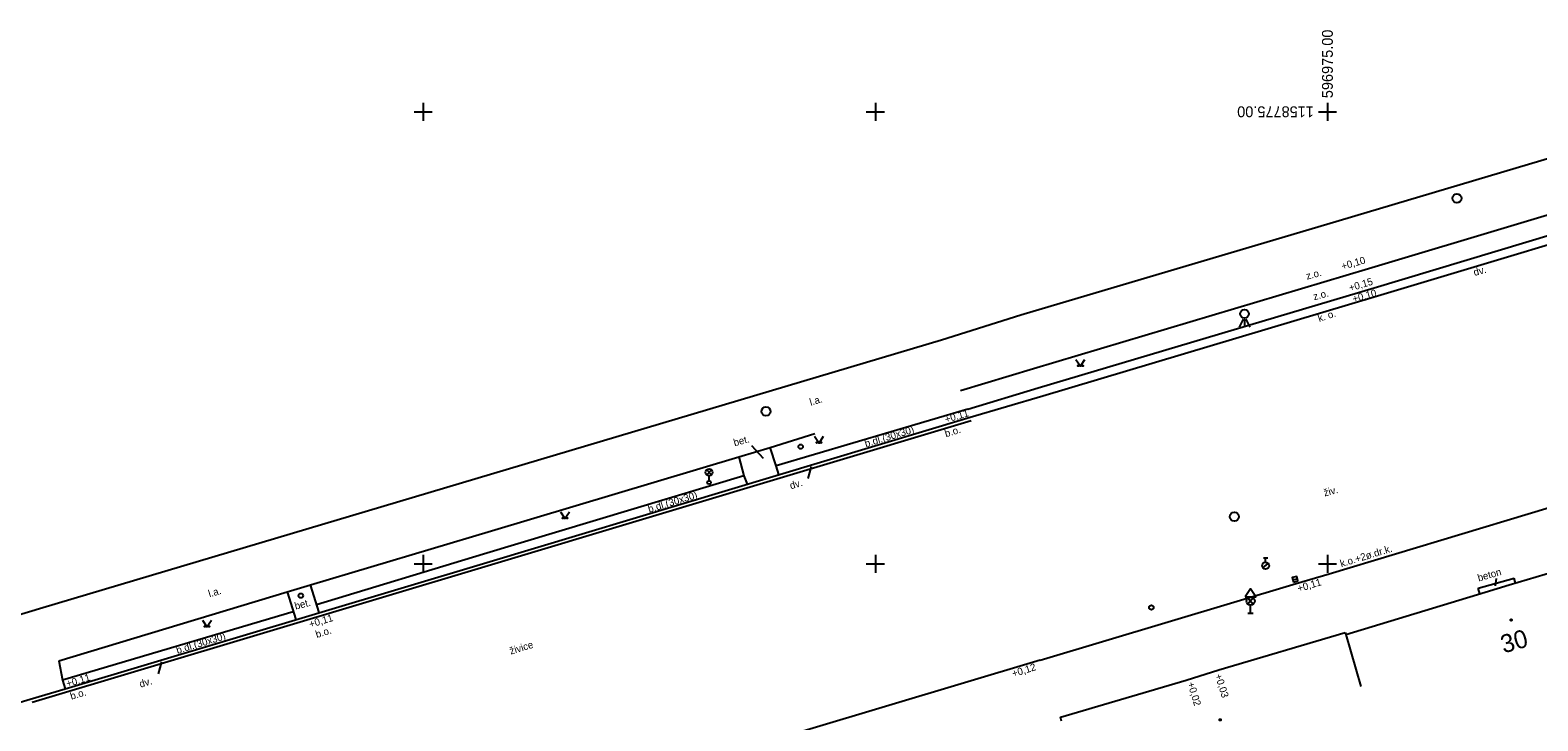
# Model space of a CAD drawing. Extents: x -597333 to -596488, y -1158921 to -1158644.
# Drawn here: x -597046.7 to -596963.4, y -1158808.7 to -1158770.5 of the extents above; entities that cross this region are included whole.
import ezdxf

# ---------------------------------------------------------------- set-up
doc = ezdxf.new("R2010")
doc.units = 0
for name, color, linetype in [('Vrstva 10', 7, 'Continuous'), ('Vrstva 14', 7, 'Continuous'), ('Vrstva 15', 7, 'Continuous'), ('Vrstva 23', 7, 'Continuous'), ('Vrstva 24', 7, 'Continuous'), ('Vrstva 25', 7, 'Continuous'), ('Vrstva 29', 7, 'Continuous'), ('Vrstva 4', 7, 'Continuous'), ('Vrstva 43', 7, 'Continuous'), ('Vrstva 44', 7, 'Continuous'), ('Vrstva 49', 7, 'Continuous'), ('Vrstva 5', 7, 'Continuous'), ('Vrstva 50', 7, 'Continuous'), ('Vrstva 52', 7, 'Continuous'), ('Vrstva 62', 7, 'Continuous'), ('Vrstva 7', 7, 'Continuous')]:
    doc.layers.add(name, color=color, linetype=linetype)

msp = doc.modelspace()

# ---------------------------------------------------------------- linework, layer by layer
at = {"layer": 'Vrstva 10'}
msp.add_line((-597046.039, -1158802.404), (-596996.341, -1158787.614), dxfattribs=at)
for points in [[(-596974.355, -1158781.01), (-596957.875, -1158776.104), (-596940.288, -1158770.868)], [(-596996.341, -1158787.614), (-596991.949, -1158786.233), (-596974.355, -1158781.01)], [(-597053.2, -1158804.562), (-597046.039, -1158802.404)]]:
    msp.add_lwpolyline(points, dxfattribs=at)
at = {"layer": 'Vrstva 14'}
for points in [[(-596988.908, -1158788.694), (-596988.658, -1158789.069), (-596988.408, -1158788.694)], [(-597003.365, -1158792.945), (-597003.115, -1158793.32), (-597002.865, -1158792.945)], [(-597017.415, -1158797.12), (-597017.165, -1158797.495), (-597016.915, -1158797.12)], [(-597037.211, -1158803.103), (-597036.961, -1158803.478), (-597036.711, -1158803.103)]]:
    msp.add_lwpolyline(points, dxfattribs=at)
for centre in [(-596988.783, -1158789.044), (-596988.533, -1158789.044), (-597003.24, -1158793.295), (-597002.99, -1158793.295), (-597017.29, -1158797.47), (-597017.04, -1158797.47), (-597037.086, -1158803.453), (-597036.836, -1158803.453)]:
    msp.add_circle(centre, 0.025, dxfattribs=at)
at = {"layer": 'Vrstva 15'}
for centre in [(-596964.837, -1158803.105), (-596980.931, -1158808.622)]:
    msp.add_circle(centre, 0.0438, dxfattribs=at)
at = {"layer": 'Vrstva 23'}
for centre in [(-597004.13, -1158793.519), (-597031.776, -1158801.758)]:
    msp.add_circle(centre, 0.125, dxfattribs=at)
at = {"layer": 'Vrstva 24'}
for p, q in [((-596978.542, -1158799.66), (-596978.292, -1158799.66)), ((-596978.417, -1158799.91), (-596978.417, -1158799.66)), ((-596978.564, -1158800.214), (-596978.269, -1158799.982))]:
    msp.add_line(p, q, dxfattribs=at)
for centre, radius in [((-596978.417, -1158800.098), 0.188), ((-596984.734, -1158802.408), 0.125)]:
    msp.add_circle(centre, radius, dxfattribs=at)
at = {"layer": 'Vrstva 25'}
msp.add_line((-596976.911, -1158800.881), (-596976.669, -1158800.819), dxfattribs=at)
msp.add_lwpolyline([(-596976.88, -1158801.003), (-596976.638, -1158800.941), (-596976.7, -1158800.698), (-596976.942, -1158800.76)], close=True, dxfattribs=at)
for centre in [(-596967.839, -1158779.786), (-597006.05, -1158791.571), (-596980.144, -1158797.39)]:
    msp.add_circle(centre, 0.25, dxfattribs=at)
at = {"layer": 'Vrstva 29'}
for p, q in [((-597009.328, -1158795.069), (-597009.064, -1158794.805)), ((-597009.06, -1158795.068), (-597009.324, -1158794.803)), ((-597009.196, -1158795.4), (-597009.196, -1158795.125))]:
    msp.add_line(p, q, dxfattribs=at)
for centre, radius in [((-597009.196, -1158794.938), 0.188), ((-597009.196, -1158795.5), 0.1)]:
    msp.add_circle(centre, radius, dxfattribs=at)
at = {"layer": 'Vrstva 4'}
for p, q in [((-596964.94, -1158801.16), (-596951.99, -1158797.3)), ((-596973.98, -1158803.9), (-596966.28, -1158801.56)), ((-596981.01, -1158805.86), (-596974.01, -1158803.8)), ((-596974.01, -1158803.8), (-596973.98, -1158803.9)), ((-596973.98, -1158803.9), (-596973.149, -1158806.782)), ((-596982.82, -1158806.42), (-596981.01, -1158805.86))]:
    msp.add_line(p, q, dxfattribs=at)
msp.add_lwpolyline([(-596989.7, -1158808.7), (-596989.769, -1158808.465), (-596982.82, -1158806.42)], dxfattribs=at)
at = {"layer": 'Vrstva 44'}
for p, q in [((-596979.661, -1158786.465), (-596979.887, -1158786.917)), ((-596979.587, -1158786.467), (-596979.587, -1158786.917)), ((-596979.512, -1158786.465), (-596979.287, -1158786.917)), ((-596979.1, -1158801.88), (-596979.4, -1158802.224)), ((-596979.4, -1158801.88), (-596979.1, -1158802.224)), ((-596979.25, -1158802.73), (-596979.25, -1158802.28)), ((-596979.4, -1158802.73), (-596979.1, -1158802.73))]:
    msp.add_line(p, q, dxfattribs=at)
msp.add_lwpolyline([(-596979.55, -1158801.824), (-596978.95, -1158801.824), (-596979.25, -1158801.374), (-596979.55, -1158801.824)], dxfattribs=at)
for centre, radius in [((-596979.587, -1158786.172), 0.234), ((-596979.25, -1158802.052), 0.228)]:
    msp.add_circle(centre, radius, dxfattribs=at)
at = {"layer": 'Vrstva 49'}
msp.add_line((-596965.667, -1158800.809), (-596965.725, -1158801.21), dxfattribs=at)
for points in [[(-597006.843, -1158793.46), (-597006.213, -1158794.158)], [(-597003.542, -1158794.608), (-597003.731, -1158795.273)], [(-597039.469, -1158805.409), (-597039.658, -1158806.074)]]:
    msp.add_lwpolyline(points, dxfattribs=at)
at = {"layer": 'Vrstva 5'}
msp.add_line((-596966.28, -1158801.56), (-596964.94, -1158801.16), dxfattribs=at)
at = {"layer": 'Vrstva 62'}
for p, q in [((-597025, -1158774.5), (-597025, -1158775.5)), ((-597000, -1158774.5), (-597000, -1158775.5)), ((-596975, -1158774.5), (-596975, -1158775.5)), ((-597025.5, -1158775), (-597024.5, -1158775)), ((-597000.5, -1158775), (-596999.5, -1158775)), ((-596975.5, -1158775), (-596974.5, -1158775)), ((-597025, -1158799.5), (-597025, -1158800.5)), ((-597000, -1158799.5), (-597000, -1158800.5)), ((-596975, -1158799.5), (-596975, -1158800.5)), ((-597025.5, -1158800), (-597024.5, -1158800)), ((-597000.5, -1158800), (-596999.5, -1158800)), ((-596975.5, -1158800), (-596974.5, -1158800))]:
    msp.add_line(p, q, dxfattribs=at)
at = {"layer": 'Vrstva 7'}
for p, q in [((-597030.763, -1158802.692), (-597031.245, -1158801.164)), ((-596966.576, -1158801.65), (-596966.67, -1158801.34)), ((-596964.597, -1158801.058), (-596964.68, -1158800.78)), ((-597032.526, -1158801.546), (-597032.056, -1158803.079))]:
    msp.add_line(p, q, dxfattribs=at)
for points in [[(-596972.734, -1158783.666), (-596955.692, -1158778.558), (-596939.383, -1158773.67)], [(-596972.419, -1158784.735), (-596955.638, -1158779.693), (-596939.072, -1158774.716)], [(-596972.236, -1158785.184), (-596955.399, -1158780.132), (-596938.929, -1158775.19)], [(-596990.878, -1158805.314), (-596976.73, -1158801.09), (-596974.91, -1158800.54), (-596952.89, -1158793.91), (-596936.83, -1158789.11), (-596932.27, -1158787.72), (-596914.48, -1158782.39), (-596902.66, -1158778.86), (-596901.59, -1158778.56)], [(-596995.287, -1158790.407), (-596991.262, -1158789.204), (-596972.734, -1158783.666)], [(-596994.893, -1158791.451), (-596991.001, -1158790.27), (-596972.419, -1158784.735)], [(-596994.748, -1158791.88), (-596990.732, -1158790.712), (-596972.236, -1158785.184)], [(-596994.696, -1158792.081), (-597021.416, -1158800.114), (-597046.636, -1158807.668)], [(-597044.811, -1158806.9), (-597021.487, -1158799.913), (-596994.748, -1158791.88)], [(-596994.893, -1158791.451), (-597005.482, -1158794.571)], [(-597045.155, -1158805.365), (-597032.526, -1158801.546), (-597031.245, -1158801.164), (-597021.233, -1158798.164), (-597007.552, -1158794.079), (-597005.823, -1158793.57), (-597003.355, -1158792.789)], [(-597005.332, -1158795.06), (-597005.482, -1158794.571), (-597005.823, -1158793.57)], [(-597007.552, -1158794.079), (-597007.274, -1158795.132), (-597007.092, -1158795.588)], [(-597007.274, -1158795.132), (-597021.661, -1158799.469), (-597030.901, -1158802.254)], [(-596966.67, -1158801.34), (-596964.68, -1158800.78)], [(-597032.188, -1158802.648), (-597044.956, -1158806.425)], [(-597045.155, -1158805.365), (-597044.956, -1158806.425), (-597044.811, -1158806.9)], [(-596990.878, -1158805.314), (-597008, -1158810.443), (-597008.301, -1158810.523)], [(-597054.804, -1158809.902), (-597046.743, -1158807.484), (-597044.811, -1158806.9)]]:
    msp.add_lwpolyline(points, dxfattribs=at)

# ---------------------------------------------------------------- texts
at = {"layer": 'Vrstva 43'}
msp.add_text('30', height=1, rotation=15.68677, dxfattribs=at).set_placement((-596965.258, -1158804.953))
at = {"layer": 'Vrstva 49'}
for s, rotation, p in [('z.o.', 15, (-596976.124, -1158784.287)), ('dv.', 15, (-596966.865, -1158784.081)), ('z.o.', 15, (-596975.73, -1158785.426)), ('k. o.', 18.50531, (-596975.452, -1158786.63)), ('l.a.', 16.84381, (-597003.569, -1158791.259)), ('bet.', 14.94116, (-597007.786, -1158793.498)), ('b.dl.(30x30)', 16.84381, (-597000.522, -1158793.555)), ('b.o.', 16.75917, (-596996.096, -1158792.997)), ('dv.', 16.84381, (-597004.667, -1158795.88)), ('b.dl.(30x30)', 16.84381, (-597012.506, -1158797.172)), ('živ.', 14.62948, (-596975.151, -1158796.272)), ('k.o.+2ø.dr.k.', 16.95227, (-596974.23, -1158800.185)), ('beton', 15.80982, (-596966.632, -1158800.973)), ('l.a.', 16.84381, (-597036.819, -1158801.853)), ('bet.', 14.94116, (-597032.057, -1158802.536)), ('b.dl.(30x30)', 16.84381, (-597038.595, -1158804.98)), ('b.o.', 16.75917, (-597030.892, -1158804.099)), ('živice', 16.84381, (-597020.16, -1158805.016)), ('dv.', 16.84381, (-597040.638, -1158806.847)), ('b.o.', 16.75917, (-597044.46, -1158807.517))]:
    msp.add_text(s, height=0.4, rotation=rotation, dxfattribs=at).set_placement(p)
at = {"layer": 'Vrstva 50'}
for s, rotation, p in [('+0,10', 15.87762, (-596974.167, -1158783.746)), ('+0,15', 16.65768, (-596973.747, -1158784.941)), ('+0,10', 15.49142, (-596973.552, -1158785.551)), ('+0,11', 16.6233, (-596996.094, -1158792.213)), ('+0,11', 16.79308, (-596976.592, -1158801.562)), ('+0,11', 16.6233, (-597031.252, -1158803.536)), ('+0,12', 17.42841, (-596992.374, -1158806.269)), ('+0,11', 16.6233, (-597044.678, -1158806.824)), ('+0,03', 287.58258, (-596981.232, -1158806.15)), ('+0,02', 286.98675, (-596982.749, -1158806.597))]:
    msp.add_text(s, height=0.4, rotation=rotation, dxfattribs=at).set_placement(p)
at = {"layer": 'Vrstva 52'}
for s, rotation, p in [('596975.00', 90, (-596974.7, -1158774.25)), ('1158775.00', 180, (-596975.75, -1158774.7))]:
    msp.add_text(s, height=0.6, rotation=rotation, dxfattribs=at).set_placement(p)

doc.saveas('drawing.dxf')
